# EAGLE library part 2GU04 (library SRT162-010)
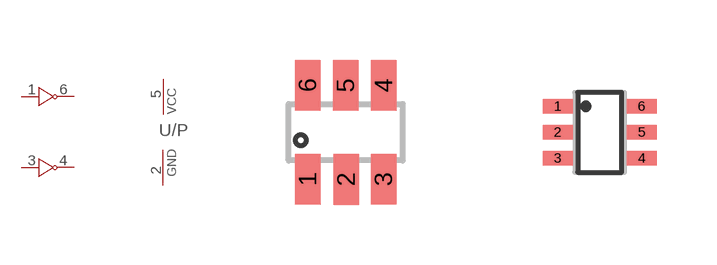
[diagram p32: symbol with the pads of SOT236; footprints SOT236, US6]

Designator prefix U; gates /1=INV /2=INV /P=PWRN

## 2GU04  [SOT236]
1  /1:1  in
2  /P:GND  pwr
3  /2:1  in
4  /2:2  out
5  /P:VCC  pwr
6  /1:2  out

## 2GU04US6  [US6]
Pads as for SOT236

## 2GU04SOT236+US6  [SOU236-US6]
Pads as for SOT236

## Footprint SOT236 (pad centres in mm)
smd 0.635 x 1.27: 1 -0.95,-1.175; 2 0.013,-1.185; 3 0.95,-1.175; 4 0.95,1.175; 5 0,1.175; 6 -0.95,1.175

## Footprint US6 (pad centres in mm)
0.65 mm pitch narrow (1.25 mm) width package
smd 0.762 x 0.356: 1 -1.05,0.65; 2 -1.05,0; 3 -1.05,-0.65; 4 1.05,-0.65; 5 1.05,0; 6 1.05,0.65

## Footprint SOU236-US6 (pad centres in mm)
smd 0.762 x 1.27: 1 -0.95,-1.175; 3 0.95,-1.175; 4 0.95,1.175; 6 -0.95,1.175
smd 0.508 x 1.27: 2 0.013,-1.185; 5 0,1.175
